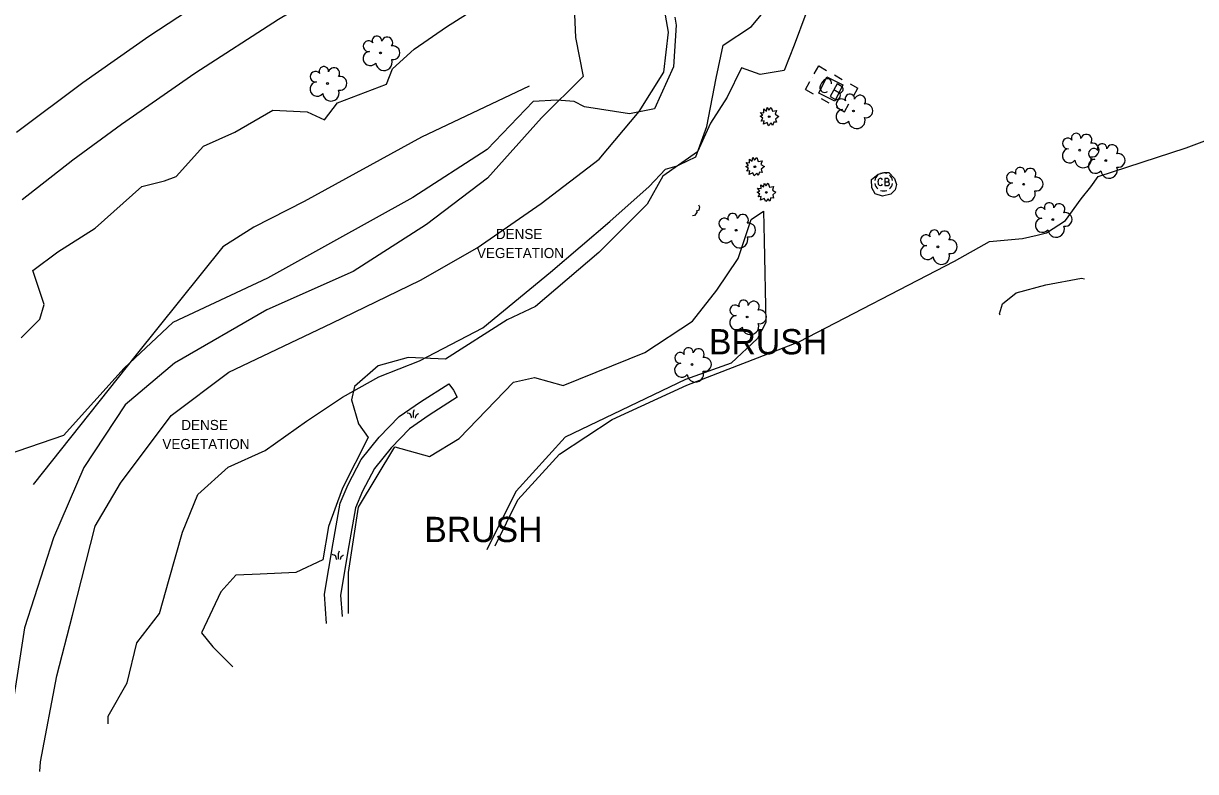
# Model space of a CAD drawing. Extents: x 2129547 to 2134906, y 657330 to 659734.
# Drawn here: x 2132780.8 to 2133105.8, y 658259.2 to 658466.7 of the extents above; entities that cross this region are included whole.
import ezdxf

# ---------------------------------------------------------------- set-up
doc = ezdxf.new("R2010")
doc.units = 0
for name, color, linetype in [('Default', 7, 'Continuous'), ('DR_X_Cells', 7, 'Continuous'), ('DR_X_Culvert', 7, 'Continuous'), ('DT_X_Island', 7, 'Continuous'), ('HY_X_Wetland_Area', 7, 'Continuous'), ('HY_X_Wetland_Cells', 7, 'Continuous'), ('PM_X_Edge_Line', 7, 'Continuous'), ('PV_X_Parking_Lot', 7, 'Continuous'), ('RD_X_Concrete_Pad', 7, 'Continuous'), ('RD_X_Fence', 7, 'Continuous'), ('RD_X_Misc_Items', 7, 'Continuous'), ('VG_X_Cells', 7, 'Continuous'), ('VG_X_Shrub_Line_Lt', 7, 'Continuous'), ('VG_X_Text', 7, 'Continuous'), ('VG_X_Tree_Line_Lt', 7, 'Continuous')]:
    doc.layers.add(name, color=color, linetype=linetype)

# ---------------------------------------------------------------- blocks, each defined once
blk = doc.blocks.new('CULVERT')
at = {"layer": 'Default'}
blk.add_lwpolyline([(-0.0508, 0.1143), (0, 0.0635), (0, -0.0635), (-0.0508, -0.1143)], dxfattribs=at)
blk = doc.blocks.new('SHRUB')
at = {"layer": 'VG_X_Cells'}
blk.add_lwpolyline([(-0.0011, 0.023), (0.0066, 0.0323), (0.0119, 0.0189), (0.0257, 0.0212), (0.0214, 0.0084), (0.0334, 0.0008), (0.0226, -0.0085), (0.0257, -0.0201), (0.0162, -0.0192), (0.012, -0.0308), (0.0066, -0.0221), (-0.002, -0.0324), (-0.0075, -0.0212), (-0.0204, -0.0266), (-0.018, -0.0147), (-0.0283, -0.0157), (-0.0223, -0.0057), (-0.032, 0.0015), (-0.0226, 0.0049), (-0.0304, 0.0151), (-0.0185, 0.0137), (-0.0189, 0.0269), (-0.0093, 0.0196), (-0.0067, 0.0322), (-0.0011, 0.023)], dxfattribs=at)
blk.add_circle((0, 0), 0.00293, dxfattribs=at)
blk = doc.blocks.new('TREE')
at = {"layer": 'VG_X_Cells'}
blk.add_circle((0, 0), 0.00305, dxfattribs=at)
for centre, radius, start, end in [((-0.042, 0.0237), 0.0187, 39.0625, 279.5412), ((-0.0125, 0.0428), 0.0167, 354.0047, 205.9741), ((0.0232, 0.0359), 0.0197, 323.83, 165.0376), ((-0.0362, -0.0197), 0.0251, 96.1722, 320.5737), ((0.0439, 0.0005), 0.0243, 259.1453, 101.4596), ((0.012, -0.0331), 0.029, 184.9476, 19.4572)]:
    blk.add_arc(centre, radius, start, end, dxfattribs=at)
blk = doc.blocks.new('SWAMP')
at = {"layer": 'Default'}
for points in [[(-0.0222, 0.017), (-0.0215, 0.0168), (-0.0209, 0.0165), (-0.0157, 0.0153), (-0.0151, 0.0151), (-0.0146, 0.0149), (-0.0142, 0.0147), (-0.0138, 0.0145), (-0.0132, 0.0141), (-0.0127, 0.0138), (-0.0124, 0.0135), (-0.012, 0.0131), (-0.0117, 0.0125), (-0.0112, 0.0117), (-0.0108, 0.011), (-0.0105, 0.0102), (-0.0099, 0.0089), (-0.0095, 0.0076), (-0.0092, 0.0066), (-0.0087, 0.0047), (-0.008, 0.0018), (-0.0076, 0.0004), (-0.0072, -0.001)], [(0, 0), (0, 0.006), (0, 0.012), (0, 0.0149), (0.0001, 0.016), (0.0001, 0.0169), (0.0002, 0.0177), (0.0004, 0.0192), (0.0006, 0.0202), (0.0007, 0.021), (0.0011, 0.0222), (0.0013, 0.0227), (0.0015, 0.0233), (0.0026, 0.0259), (0.0037, 0.0286)], [(0.007, -0.0018), (0.0074, -0.0006), (0.0085, 0.0037), (0.0088, 0.0048), (0.0091, 0.0056), (0.0095, 0.0068), (0.0098, 0.0074), (0.0101, 0.0079), (0.0103, 0.0085), (0.0107, 0.0089), (0.011, 0.0093), (0.0113, 0.0097), (0.0117, 0.01), (0.0123, 0.0106), (0.013, 0.011), (0.0141, 0.0118), (0.0159, 0.0128), (0.0167, 0.0134), (0.0175, 0.014)]]:
    blk.add_lwpolyline(points, dxfattribs=at)
blk = doc.blocks.new('POINT_DISPLAY')
at = {"layer": 'Default'}
blk.add_line((0, 0), (0, 0), dxfattribs=at)
blk = doc.blocks.new('CBRND-X')
at = {"layer": 'Default'}
blk.add_line((0.034, 0.007), (0.124, 0.007), dxfattribs=at)
blk.add_lwpolyline([(0.116, 0.099), (0.034, 0.099), (0.034, -0.104), (0.124, -0.104)], dxfattribs=at)
for centre, radius, start, end in [((0, 0), 0.254, 130.0806, 170.0721), ((0.071, 0), 0.233, 164.8107, 195.1893), ((-0.093, 0.038), 0.0645, 21.5603, 158.4397), ((0, 0), 0.254, 70.0577, 110.1061), ((0.101, 0.051), 0.0501, 296.8207, 73.0013), ((0.101, -0.049), 0.0597, 292.0547, 67.9453), ((0, 0), 0.254, 10.0169, 50.0392), ((0, 0), 0.254, 190.0169, 230.0392), ((-0.093, -0.037), 0.0645, 201.5603, 338.4397), ((0, 0), 0.254, 250.0577, 290.0473), ((0, 0), 0.254, 310.0114, 350.0264)]:
    blk.add_arc(centre, radius, start, end, dxfattribs=at)
blk.add_blockref('POINT_DISPLAY', (0, 0), dxfattribs=at)
blk.add_blockref('POINT_DISPLAY', (0, 0), dxfattribs=at)
blk.add_blockref('POINT_DISPLAY', (0, 0), dxfattribs=at)
blk.add_blockref('POINT_DISPLAY', (0, 0), dxfattribs=at)
blk = doc.blocks.new('GCB-X')
at = {"layer": 'Default'}
for p, q in [((-0.0317, 0.019), (-0.019, 0.019)), ((-0.0317, 0.0063), (-0.0317, 0.019)), ((-0.0063, 0.019), (0.0063, 0.019)), ((0.019, 0.019), (0.0317, 0.019)), ((0.0317, 0.0063), (0.0317, 0.019)), ((0.0034, 0.0007), (0.0124, 0.0007)), ((-0.0317, -0.019), (-0.0317, -0.0063)), ((0.0317, -0.019), (0.0317, -0.0063)), ((-0.0317, -0.019), (-0.019, -0.019)), ((-0.0063, -0.019), (0.0063, -0.019)), ((0.019, -0.019), (0.0317, -0.019))]:
    blk.add_line(p, q, dxfattribs=at)
blk.add_lwpolyline([(0.0116, 0.0099), (0.0034, 0.0099), (0.0034, -0.0104), (0.0124, -0.0104)], dxfattribs=at)
for centre, radius, start, end in [((0.0071, 0), 0.0233, 164.8107, 195.1893), ((-0.0094, 0.0037), 0.00645, 21.5603, 158.4397), ((0.0101, 0.0051), 0.00501, 296.8207, 73.0013), ((0.0101, -0.0049), 0.00597, 292.0547, 67.9453), ((-0.0094, -0.0037), 0.00645, 201.5603, 338.4397)]:
    blk.add_arc(centre, radius, start, end, dxfattribs=at)
for p in [(0, 0.019), (0, 0.019), (-0.0317, 0), (0, 0), (0, 0), (0, 0), (0.0317, 0), (0, -0.019), (0, -0.019)]:
    blk.add_blockref('POINT_DISPLAY', p, dxfattribs=at)

msp = doc.modelspace()

# ---------------------------------------------------------------- linework, layer by layer
at = {"layer": 'DT_X_Island'}
msp.add_lwpolyline([(2133020.69, 658425.31), (2133022.33, 658423.69), (2133022.83, 658422.01), (2133022.45, 658420.52), (2133021.31, 658419.34), (2133018.98, 658418.82), (2133016.96, 658419.48), (2133016.01, 658421.08), (2133015.92, 658423.41), (2133017.75, 658424.85), (2133019.53, 658425.31), (2133020.69, 658425.31)], dxfattribs=at)
at = {"layer": 'HY_X_Wetland_Area'}
msp.add_lwpolyline([(2132864.86, 658300.29), (2132864.29, 658308.41), (2132866.7, 658322.68), (2132868.65, 658333.63), (2132870.8, 658338.84), (2132874.47, 658345.74), (2132879.46, 658351.96), (2132885, 658357.69), (2132890.86, 658361.75), (2132898.73, 658366.77), (2132900.01, 658364.99), (2132901.09, 658363.05), (2132893.29, 658358.09), (2132887.86, 658354.32), (2132882.76, 658349.05), (2132878.16, 658343.31), (2132874.78, 658336.96), (2132872.9, 658332.39), (2132871.04, 658321.93), (2132868.72, 658308.19), (2132869.13, 658302.26)], dxfattribs=at)
at = {"layer": 'PM_X_Edge_Line'}
for points in [[(2132780.42, 658417.85), (2132794.53, 658428.85), (2132808.02, 658438.8), (2132828.29, 658452.89), (2132851.51, 658467.84), (2132872.43, 658480.36), (2132894.67, 658493.03), (2132919.61, 658506.34), (2132942.8, 658518.03), (2132970.58, 658531.41), (2132994.65, 658542.18), (2133023.55, 658554.71), (2133055.17, 658567.57), (2133087.49, 658580.23), (2133114.79, 658590.55), (2133143.49, 658600.71), (2133168.31, 658608.81), (2133196.23, 658617.63), (2133226.14, 658626.84), (2133262.28, 658638.19), (2133300.81, 658650.13), (2133340.17, 658662.31)], [(2132778.88, 658436.51), (2132797.28, 658450.31), (2132815.53, 658463.15), (2132834.09, 658475.32), (2132853.88, 658487.67), (2132874.62, 658499.37), (2132902.61, 658514.38), (2132925.64, 658526.53), (2132961.12, 658543.72), (2132996.4, 658559.86), (2133023.56, 658571.6), (2133058.45, 658586.09), (2133087.14, 658597.32), (2133091.83, 658599.15), (2133110.89, 658606.44), (2133134.83, 658615.24), (2133158.51, 658623.08)]]:
    msp.add_lwpolyline(points, dxfattribs=at)
at = {"layer": 'PV_X_Parking_Lot'}
for points in [[(2132911.62, 658321.81), (2132917.83, 658334.57), (2132929.45, 658347.24), (2132943.98, 658356.87), (2132964.72, 658366.4), (2132995.74, 658378.43), (2133038.89, 658400.73), (2133048.63, 658406.18), (2133057.81, 658407.03), (2133061.83, 658407.99), (2133064.42, 658408.61), (2133069.68, 658412.04), (2133074.06, 658418.09), (2133076.69, 658421.35), (2133078.77, 658424.21), (2133103.14, 658432.24), (2133116.7, 658437.31)], [(2133051.58, 658385.83), (2133051.4, 658386.15), (2133052.22, 658388.93), (2133056.04, 658391.98), (2133064.24, 658394.25), (2133074.14, 658396.06), (2133075, 658395.84)]]:
    msp.add_lwpolyline(points, dxfattribs=at)
at = {"layer": 'RD_X_Concrete_Pad'}
msp.add_lwpolyline([(2133005.74, 658445.18), (2133001.31, 658447.37), (2133003.55, 658451.88), (2133007.97, 658449.69)], close=True, dxfattribs=at)
at = {"layer": 'RD_X_Fence'}
msp.add_lwpolyline([(2132920.98, 658449.29), (2132891.14, 658435.11), (2132858.67, 658417.29), (2132844.64, 658410.17), (2132836.06, 658404.76), (2132812.09, 658374.8), (2132783.54, 658338.88)], dxfattribs=at)
at = {"layer": 'RD_X_Misc_Items'}
for points in [[(2132804.33, 658272.44), (2132804.29, 658274.63), (2132809.55, 658283.83), (2132812.28, 658294.92), (2132818.5, 658303.07), (2132821.18, 658312.62), (2132824.88, 658325.61), (2132829.18, 658336.07), (2132837.59, 658343.65), (2132847.86, 658348.25), (2132859.25, 658356.41), (2132869.27, 658363.05), (2132879.36, 658368.74), (2132890.64, 658373.15), (2132908.18, 658382.26), (2132926.89, 658397.73), (2132943.35, 658411.76), (2132954.25, 658421.52), (2132958.8, 658426.27), (2132962.03, 658427.18), (2132962.58, 658427.45), (2132967.22, 658429.67), (2132970.3, 658438.13), (2132972.88, 658451.51), (2132974.76, 658460.63), (2132982.66, 658465.8), (2132988.94, 658473.51)], [(2132961.42, 658468.45), (2132961.76, 658466.24), (2132961.02, 658454.7), (2132955.72, 658443.05), (2132948.86, 658441.64), (2132936.37, 658443.57), (2132933.49, 658445.02), (2132928.71, 658445.41), (2132922.13, 658445.06), (2132909.34, 658431.77), (2132888.74, 658418.46), (2132865.96, 658405.72), (2132848.5, 658396.07), (2132822.2, 658383.77), (2132808.72, 658371.07), (2132791.91, 658352.39), (2132769.5, 658344.74)]]:
    msp.add_lwpolyline(points, dxfattribs=at)
at = {"layer": 'VG_X_Shrub_Line_Lt'}
msp.add_lwpolyline([(2132870.95, 658303.09), (2132870.89, 658314.47), (2132873.71, 658332.56), (2132883.81, 658349.32), (2132893.37, 658346.59), (2132901.63, 658351.62), (2132916.63, 658367.23), (2132922.47, 658368.5), (2132930.46, 658366.29), (2132953.09, 658375.48), (2132966.29, 658384.12), (2132973.06, 658392.7), (2132978.95, 658401.52), (2132982.53, 658412.35), (2132985.96, 658414.66), (2132986.2, 658406.54), (2132986.62, 658383.74), (2132984.27, 658379.36), (2132977.06, 658372.45), (2132964.34, 658367.96), (2132931.04, 658352.01), (2132917.45, 658336.95), (2132912.3, 658326.91), (2132909.29, 658320.74)], dxfattribs=at)
at = {"layer": 'VG_X_Tree_Line_Lt'}
for points in [[(2132785.4, 658259.25), (2132785.52, 658261.97), (2132790.07, 658285.8), (2132794.38, 658302.64), (2132800.69, 658327.27), (2132807.7, 658339.21), (2132821.81, 658358.01), (2132837.79, 658369.99), (2132866.3, 658383.61), (2132890.87, 658395.47), (2132906.63, 658404.43), (2132924.3, 658416.79), (2132940.45, 658429.07), (2132951.51, 658442.24), (2132958.37, 658453.14), (2132959.64, 658464.26), (2132957.08, 658479.1)], [(2132780.17, 658379.55), (2132785.31, 658384.71), (2132786.59, 658388.76), (2132783.46, 658398.22), (2132790.33, 658403.38), (2132800.72, 658409.89), (2132813.63, 658421.51), (2132819.92, 658423.03), (2132823.19, 658424.22), (2132830.73, 658432.62), (2132839.42, 658436.57), (2132849.99, 658442.61), (2132859.49, 658442.14), (2132864.31, 658439.94), (2132867.9, 658444.69), (2132881.42, 658449.88), (2132883.16, 658454.08), (2132889.1, 658459.51), (2132898.07, 658465.78), (2132910.24, 658473.54)], [(2132933.57, 658469.15), (2132933.87, 658462.79), (2132935.95, 658451.96), (2132924.39, 658440.47), (2132909.42, 658423.8), (2132892.57, 658410.94), (2132872.25, 658397.93), (2132848.26, 658387.24), (2132822.72, 658372.49), (2132808.98, 658360.97), (2132797.56, 658343.52), (2132789.11, 658324.08), (2132781.08, 658299.14), (2132776.72, 658270.92)], [(2132997.71, 658469.31), (2132994.49, 658460.63), (2132991.68, 658453.64), (2132985.03, 658452.53), (2132979.87, 658454.34), (2132975.94, 658446.28), (2132971.26, 658438.99), (2132967.67, 658431.08), (2132958.11, 658424.38), (2132953.7, 658416.6), (2132940.34, 658403.2), (2132922.75, 658388.16), (2132914.9, 658384.53), (2132897.79, 658373.56), (2132887.51, 658374.06), (2132879.16, 658371.71), (2132872.6, 658366.05), (2132871.76, 658362.33), (2132873.72, 658355.64), (2132876.36, 658351.85), (2132869.24, 658337.79), (2132865.38, 658327.16), (2132863.85, 658317.98), (2132856.34, 658314.42), (2132846.46, 658313.96), (2132839.67, 658313.69), (2132835.5, 658309.04), (2132830.18, 658297.73), (2132833.36, 658293.8), (2132838.85, 658288.32)]]:
    msp.add_lwpolyline(points, dxfattribs=at)

# ---------------------------------------------------------------- block references
at = {"layer": 'DR_X_Cells', "xscale": 196.85000000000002, "yscale": 196.85, "rotation": -29.644757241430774}
msp.add_blockref('GCB-X', (2133004.86, 658448.55), dxfattribs=at)
at = {"layer": 'DR_X_Cells', "xscale": 9.842500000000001, "yscale": 9.842500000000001}
msp.add_blockref('CBRND-X', (2133019.3, 658422.74), dxfattribs=at)
at = {"layer": 'DR_X_Culvert'}
for p, xscale, yscale, rotation in [((2132967.19, 658413.85), 7.874000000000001, 7.8740000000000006, -37.042474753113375), ((2132968.14, 658415.4), 7.8740000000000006, 7.874000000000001, -15.530164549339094)]:
    msp.add_blockref('CULVERT', p, dxfattribs=dict(at, xscale=xscale, yscale=yscale, rotation=rotation))
at = {"layer": 'HY_X_Wetland_Cells', "xscale": 78.74000000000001, "yscale": 78.74000000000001}
for p in [(2132888.94, 658357.4), (2132868.13, 658318.17)]:
    msp.add_blockref('SWAMP', p, dxfattribs=at)
at = {"layer": 'VG_X_Cells', "xscale": 78.74000000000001, "yscale": 78.74000000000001}
for name, p in [('TREE', (2132879.8, 658458.52)), ('TREE', (2132865.1, 658450.04)), ('TREE', (2133010.92, 658442.42)), ('SHRUB', (2132987.56, 658440.85)), ('TREE', (2133073.64, 658431.55)), ('TREE', (2133080.86, 658428.66)), ('SHRUB', (2132983.59, 658426.94)), ('TREE', (2133058.11, 658422.11)), ('SHRUB', (2132986.75, 658419.82)), ('TREE', (2133066.17, 658412.3)), ('TREE', (2132978.41, 658409.35)), ('TREE', (2133034.32, 658404.74)), ('TREE', (2132981.44, 658385.29)), ('TREE', (2132966.15, 658372.11))]:
    msp.add_blockref(name, p, dxfattribs=at)

# ---------------------------------------------------------------- texts
at = {"layer": 'VG_X_Text'}
for s, height, p in [('DENSE', 2.8, (2132911.78, 658406.9)), ('VEGETATION', 2.8, (2132906.54, 658401.63)), ('BRUSH', 7, (2132970.86, 658374.94)), ('DENSE', 2.8, (2132824.57, 658353.95)), ('VEGETATION', 2.8, (2132819.33, 658348.67)), ('BRUSH', 7, (2132891.94, 658322.88))]:
    msp.add_text(s, height=height, dxfattribs=at).set_placement(p)

doc.saveas('drawing.dxf')
